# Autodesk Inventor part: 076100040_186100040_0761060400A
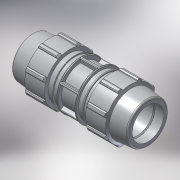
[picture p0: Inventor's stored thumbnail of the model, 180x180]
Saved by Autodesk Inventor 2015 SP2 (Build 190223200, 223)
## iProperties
Created: 2017-02
Part Number: 076100040_186100040_0761060400A
Material: PVC-Piping
Description: PLASSON REPAIR COUPLER 40
Document SubType Name: Modeling
Designer: KIM
Mass: 8658.36 g
Surface Area: 5623.3 cm^2
Volume: 6184.54 cm^3
Density: 1.4 g/cm^3
Appearance: Smooth - White
Author: KIM
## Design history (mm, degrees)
derived "07610.ipt"
feature "Solid1::07610.ipt"
tag "TaggingFeature1"
body "Solid1"
other parameters: "d1" = 215, "d4" = 17.91667, "d5" = 30.71429, "d7" = 82, "d8" = 61.5, "d9" = 30.71429, "d11" = 3.48571, "d12" = 65.6, "d13" = 120 deg, "d15" = 10 deg, "d16" = 73.8, "d18" = 2, "d19" = 35 deg, "d20" = 17.5 deg, "d21" = 76.26, "d23" = 0, "d25" = 360 deg, "d27" = 1.64, "d33" = 0.8, "d34" = 4.1, "d36" = 0, "d37" = 0.8, "d38" = 0.8, "d40" = 360 deg, "d42" = 38.7, "d43" = 2.46, "d46" = 1.2, "d50" = 8.08571, "d51" = 65.6, "E_" = 82, "H_" = 215, "l_" = 148, "d49" = 19.65714
